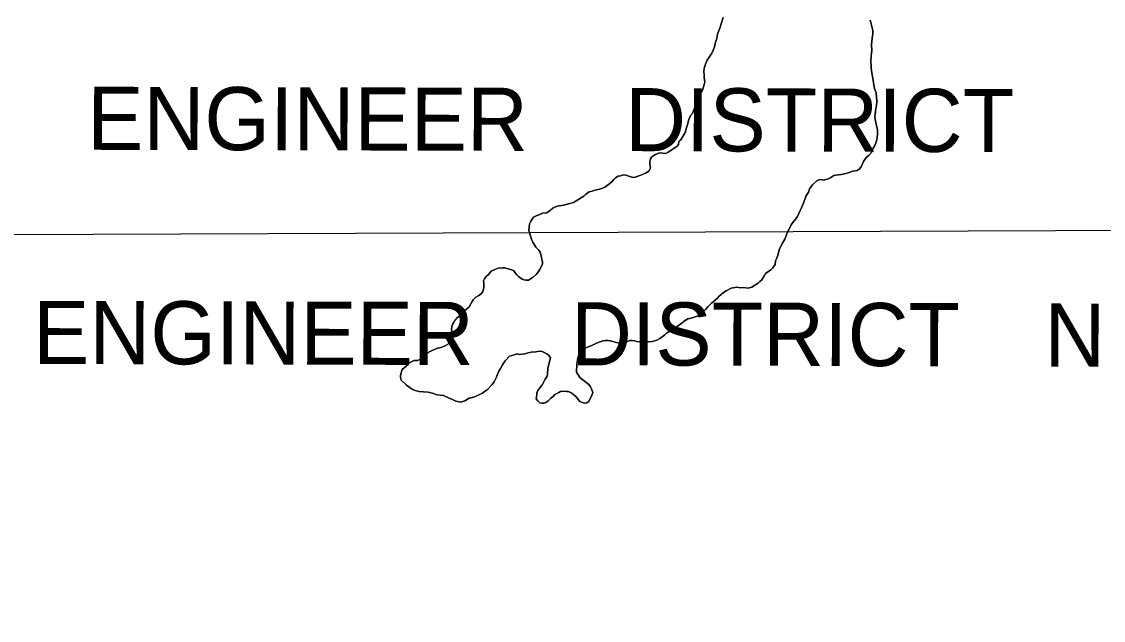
# Model space of a CAD drawing. Extents: x 3172297 to 3210190, y 958463 to 983887.
# Drawn here: x 3188356 to 3190071, y 963866 to 964815 of the extents above; entities that cross this region are included whole.
import ezdxf

# ---------------------------------------------------------------- set-up
doc = ezdxf.new("R2010")
doc.units = 0
for name, color, linetype in [('V-SITE-VEGE', 7, 'Continuous'), ('V-TOPO-BNDY', 7, 'Continuous'), ('V-TOPO-GNAM-IDEN', 7, 'Continuous'), ('V-TOPO-SHOR', 7, 'Continuous')]:
    doc.layers.add(name, color=color, linetype=linetype)

msp = doc.modelspace()

# ---------------------------------------------------------------- linework, layer by layer
at = {"layer": 'V-SITE-VEGE'}
for points in [[(3189182, 964431.1), (3189181.9, 964434.5), (3189180.9, 964438.3), (3189180.2, 964442.1), (3189178.5, 964449.7), (3189176.4, 964452.8), (3189171.5, 964457.9), (3189166.7, 964465.5), (3189164.6, 964470.3), (3189163.2, 964475.5), (3189160.4, 964484.4), (3189160.8, 964489.6), (3189161.4, 964494.8), (3189163.5, 964499.2), (3189167.9, 964505.5), (3189172.1, 964507.5), (3189177.9, 964509.6), (3189182, 964511.4), (3189188.9, 964512.4), (3189194.4, 964516.2), (3189198.2, 964519.7), (3189201.3, 964521.4), (3189205.1, 964522.5), (3189215.1, 964524.2), (3189231.2, 964528.4), (3189247.4, 964538.8), (3189250.1, 964541.2), (3189256, 964545.7), (3189260.8, 964546.7), (3189264.9, 964548.1), (3189272.2, 964549.5), (3189275.6, 964550.6), (3189279.7, 964552.3), (3189282.5, 964553.7), (3189288.7, 964558.6), (3189293.1, 964562.4), (3189295.2, 964565.1), (3189297.6, 964567.5), (3189302.1, 964570.3), (3189305.8, 964571), (3189310.3, 964572.4), (3189313.8, 964572.1), (3189323.8, 964568.7), (3189327.2, 964568.3), (3189330.3, 964569), (3189334.4, 964570.8), (3189340.3, 964572.8), (3189345.1, 964575.3), (3189350.3, 964578.4), (3189353, 964583.2), (3189352.3, 964589.1), (3189352.3, 964593.2), (3189353.3, 964597.7), (3189354.7, 964600.4), (3189360.5, 964604.9), (3189368.1, 964607.4), (3189377.4, 964606.4), (3189381.2, 964608.1), (3189394.9, 964617.5), (3189397.7, 964620.6), (3189398.3, 964625), (3189399.7, 964626.8), (3189401.1, 964627.8), (3189407.9, 964639.5), (3189410.3, 964647.1), (3189412, 964651.9), (3189412.7, 964656.4), (3189413.7, 964659.9), (3189416.8, 964666.4), (3189419.5, 964669.9), (3189423.6, 964679.9), (3189424, 964685.1), (3189425.3, 964690.2), (3189429.4, 964697.1), (3189433.2, 964703), (3189435.3, 964706.8), (3189437.6, 964713.7), (3189439.4, 964719.9), (3189438.7, 964723.7), (3189438.3, 964727.5), (3189438.3, 964730.9), (3189437.6, 964736.4), (3189438.2, 964741.6), (3189440.3, 964748.1), (3189443, 964754.4), (3189445.1, 964757.5), (3189448.5, 964761.9), (3189450.6, 964765.1), (3189452.6, 964769.9), (3189454, 964773.7), (3189455.7, 964779.5), (3189456.4, 964782.6), (3189458.1, 964788.8), (3189458.7, 964792.6), (3189460.1, 964797.1), (3189462.8, 964804.7), (3189468.3, 964821.6)], [(3189701.5, 964817.5), (3189702.2, 964814.1), (3189705.3, 964801.4), (3189705.4, 964795.8), (3189704.7, 964789.3), (3189703.3, 964779), (3189703.7, 964769), (3189703.4, 964765.2), (3189702.7, 964762.1), (3189702.7, 964758), (3189702.4, 964754.8), (3189702.8, 964741.8), (3189703.8, 964734.2), (3189706.3, 964722.5), (3189707.3, 964714.9), (3189708.4, 964709.4), (3189710.8, 964702.2), (3189711.9, 964689.1), (3189711.2, 964681.9), (3189710.2, 964677.7), (3189709.5, 964673.6), (3189708.5, 964664.3), (3189709.6, 964657.7), (3189712.7, 964643.6), (3189713.1, 964636.4), (3189712.1, 964627.8), (3189710.4, 964623.3), (3189708, 964618.1), (3189705.9, 964614.7), (3189703.2, 964607.8), (3189699.4, 964602.9), (3189695, 964599.8), (3189690.9, 964593.6), (3189686.8, 964585.3), (3189684, 964581.2), (3189680.9, 964579.1), (3189673.7, 964578.1), (3189667.8, 964576), (3189662.7, 964574.6), (3189655.1, 964572.8), (3189646.8, 964572.1), (3189643.7, 964571.1), (3189638.9, 964568.3), (3189634.5, 964566.2), (3189627.6, 964564.1), (3189622.8, 964564.8), (3189619.7, 964564.4), (3189616.9, 964562.7), (3189609.7, 964556.8), (3189605.2, 964550.3), (3189603.5, 964544.8), (3189599.4, 964538.5), (3189598.4, 964534.8), (3189596.3, 964528.9), (3189591.9, 964519.2), (3189590.5, 964515.8), (3189586.1, 964506.5), (3189583.3, 964502.7), (3189578.5, 964496.8), (3189576.1, 964493), (3189572, 964484.4), (3189570.3, 964481.3), (3189566.2, 964470.6), (3189562.8, 964465.4), (3189560.7, 964461.6), (3189559, 964457.5), (3189557.3, 964454), (3189557, 964453.7), (3189554.9, 964444.7), (3189552.9, 964439.5), (3189551.2, 964436.1), (3189550.5, 964430.2), (3189546.4, 964424.4), (3189543.7, 964421.6), (3189535.4, 964416.1), (3189533.7, 964413), (3189528.9, 964405.7), (3189526.5, 964403.3), (3189523.7, 964400.9), (3189519.6, 964397.8), (3189513.8, 964394.3), (3189507.9, 964392.9), (3189500.3, 964393.6), (3189495.5, 964393.5), (3189490.7, 964394.2), (3189481.1, 964392.5), (3189473.2, 964388.3), (3189469, 964385.9), (3189461.5, 964379.3), (3189459.4, 964376.9), (3189452.5, 964371), (3189449.8, 964368.9)], [(3189159, 964290.5), (3189153.8, 964288.8), (3189144.9, 964287.7), (3189141.8, 964288.4), (3189137, 964287.3), (3189129.7, 964285.2), (3189122.9, 964277.6), (3189121.8, 964275.9), (3189120.1, 964273.8), (3189118.4, 964271.1), (3189115.3, 964265.2), (3189112.6, 964261.1), (3189109.9, 964254.9), (3189108.8, 964251.8), (3189105.1, 964244.2), (3189102, 964240), (3189094.4, 964231.7), (3189089.6, 964228.3), (3189089.3, 964228.3), (3189086.9, 964226.2), (3189073.1, 964220), (3189065.5, 964218.2), (3189059, 964214.4), (3189052.5, 964212), (3189044.5, 964213.7), (3189038.3, 964216.7), (3189033.9, 964218.4), (3189025.2, 964222.6), (3189014.5, 964223.5), (3189009, 964225.9), (3189000.8, 964228), (3188985.9, 964229), (3188978.7, 964231), (3188975.2, 964232.7), (3188972.1, 964234.8), (3188966.6, 964239.2), (3188958, 964246.8), (3188956.9, 964250.9), (3188956.9, 964254), (3188957.9, 964258.8), (3188959.3, 964263.7), (3188968.9, 964272), (3188970.3, 964273.7), (3188975.1, 964276.5), (3188978.5, 964277.9), (3188984.1, 964278.2), (3188989.2, 964280.3), (3188993.3, 964282.7), (3188998.8, 964287.9), (3189002.3, 964291.7), (3189015.3, 964297.6), (3189019.5, 964298), (3189022.6, 964299), (3189027.7, 964301.4), (3189031.2, 964303.5), (3189036, 964308.4), (3189036.6, 964315.2), (3189038, 964320.4), (3189038.3, 964323.5), (3189037.6, 964328), (3189038.3, 964331.8), (3189039.3, 964335.2), (3189040.7, 964338), (3189042.4, 964340.7), (3189046.5, 964345.6), (3189049.3, 964348), (3189054.1, 964353.2), (3189062.3, 964359.8), (3189065.8, 964362.9), (3189070.6, 964371.5), (3189072.3, 964374.3), (3189076.4, 964378.7), (3189080.9, 964381.2), (3189085.3, 964384.3), (3189087.4, 964387.4), (3189089.1, 964393.3), (3189089.1, 964400.8), (3189088.7, 964404.3), (3189090.1, 964407.7), (3189092.5, 964411.2), (3189096.6, 964414.6), (3189100.7, 964419.5), (3189106.6, 964422.6), (3189111.7, 964424.3), (3189117.9, 964425), (3189121.7, 964425.1), (3189133.1, 964422), (3189136.5, 964420.3), (3189138.9, 964417.2), (3189141.4, 964413.7), (3189144.1, 964411.3), (3189149.7, 964407.2), (3189153.1, 964405.9), (3189156.2, 964405.2), (3189159.6, 964405.5), (3189163.1, 964407.3), (3189167.2, 964410), (3189171.7, 964414.5), (3189174.4, 964417.6), (3189177.9, 964422.1), (3189182, 964431.1)], [(3189449.8, 964368.9), (3189444, 964363.1), (3189440.5, 964358.9), (3189437.4, 964355.8), (3189435, 964353.4), (3189431.9, 964351), (3189428.5, 964348.9), (3189417.5, 964345.4), (3189412.3, 964344), (3189408.2, 964341.6), (3189401, 964336.1), (3189397.6, 964333.6), (3189390, 964327.8), (3189384.8, 964325), (3189378.6, 964321.2), (3189375.2, 964318.1), (3189367.7, 964312.9), (3189363.2, 964310.4), (3189355.6, 964308.4), (3189350.1, 964307.7), (3189344.9, 964307.3), (3189340.1, 964307.3), (3189331.2, 964308.3), (3189328.1, 964309.3), (3189323.6, 964310), (3189320.5, 964309.6), (3189319.1, 964309.3), (3189314.6, 964307.5), (3189310.8, 964306.5), (3189304.3, 964305.8), (3189299.1, 964306.5), (3189295, 964307.8), (3189289.5, 964309.2), (3189285.3, 964309.9), (3189281.9, 964309.8), (3189277.8, 964309.1), (3189267.4, 964305.7), (3189262.3, 964302.9), (3189257.5, 964300.8), (3189250.2, 964298), (3189247.5, 964296.6), (3189243.4, 964293.9), (3189242.7, 964293.2), (3189238.9, 964285.6), (3189238.2, 964282.1), (3189237.2, 964278.7), (3189236.6, 964272.1), (3189235.9, 964259.7), (3189237.3, 964256.7), (3189239.7, 964253.9), (3189241.4, 964251.2), (3189255.6, 964239.8), (3189258, 964236.4), (3189259.8, 964233.3), (3189261.5, 964227.1), (3189260.1, 964223), (3189255.3, 964213.3), (3189252.3, 964210.9), (3189248.1, 964210.2), (3189243.6, 964211.9), (3189240.9, 964213.3), (3189234.7, 964220.8), (3189231.5, 964223.6), (3189230.5, 964224.9), (3189227.4, 964227), (3189223.3, 964228.7), (3189220.2, 964229), (3189214.3, 964229.4), (3189210.5, 964229), (3189207.8, 964227.3), (3189202.6, 964224.5), (3189201.6, 964224.2), (3189199.2, 964221.7), (3189195.4, 964218.6), (3189193.3, 964216.2), (3189190.2, 964213.8), (3189187.1, 964211.7), (3189184.4, 964210.3), (3189181.3, 964210.3), (3189177.9, 964211), (3189174.4, 964214.1), (3189172, 964217.5), (3189173, 964223.7), (3189173, 964226.8), (3189174.7, 964230.3), (3189181.2, 964239.6), (3189181.9, 964239.9), (3189186, 964248.6), (3189189.1, 964253.1), (3189189.8, 964256.5), (3189190.4, 964265.5), (3189191.4, 964269.9), (3189193.1, 964276.1), (3189194.5, 964282.7), (3189191.7, 964286.5), (3189189, 964288.9), (3189181.7, 964292.3), (3189177.2, 964293), (3189171.4, 964291.9), (3189163.8, 964291.2), (3189159, 964290.5)]]:
    msp.add_lwpolyline(points, dxfattribs=at)
at = {"layer": 'V-TOPO-BNDY'}
msp.add_lwpolyline([(3186048.8, 963896), (3186249.6, 964470), (3198733.3, 964517.6), (3198114.7, 963866.1)], dxfattribs=at)
at = {"layer": 'V-TOPO-SHOR'}
for points in [[(3189468.3, 964821.6), (3189462.8, 964804.7), (3189460.1, 964797.1), (3189458.7, 964792.6), (3189458.1, 964788.8), (3189456.4, 964782.6), (3189455.7, 964779.5), (3189454, 964773.7), (3189452.6, 964769.9), (3189450.6, 964765.1), (3189448.5, 964761.9), (3189445.1, 964757.5), (3189443, 964754.4), (3189440.3, 964748.1), (3189438.2, 964741.6), (3189437.6, 964736.4), (3189438.3, 964730.9), (3189438.3, 964727.5), (3189438.7, 964723.7), (3189439.4, 964719.9), (3189437.6, 964713.7), (3189435.3, 964706.8), (3189433.2, 964703), (3189429.4, 964697.1), (3189425.3, 964690.2), (3189424, 964685.1), (3189423.6, 964679.9), (3189419.5, 964669.9), (3189416.8, 964666.4), (3189413.7, 964659.9), (3189412.7, 964656.4), (3189412, 964651.9), (3189410.3, 964647.1), (3189407.9, 964639.5), (3189401.1, 964627.8), (3189399.7, 964626.8), (3189398.3, 964625), (3189397.7, 964620.6), (3189394.9, 964617.5), (3189381.2, 964608.1), (3189377.4, 964606.4), (3189368.1, 964607.4), (3189360.5, 964604.9), (3189354.7, 964600.4), (3189353.3, 964597.7), (3189352.3, 964593.2), (3189352.3, 964589.1), (3189353, 964583.2), (3189350.3, 964578.4), (3189345.1, 964575.3), (3189340.3, 964572.8), (3189334.4, 964570.8), (3189330.3, 964569), (3189327.2, 964568.3), (3189323.8, 964568.7), (3189313.8, 964572.1), (3189310.3, 964572.4), (3189305.8, 964571), (3189302.1, 964570.3), (3189297.6, 964567.5), (3189295.2, 964565.1), (3189293.1, 964562.4)], [(3189452.5, 964371), (3189459.4, 964376.9), (3189461.5, 964379.3), (3189469, 964385.9), (3189473.2, 964388.3), (3189481.1, 964392.5), (3189490.7, 964394.2), (3189495.5, 964393.5), (3189500.3, 964393.6), (3189507.9, 964392.9), (3189513.8, 964394.3), (3189519.6, 964397.8), (3189523.7, 964400.9), (3189526.5, 964403.3), (3189528.9, 964405.7), (3189533.7, 964413), (3189535.4, 964416.1), (3189543.7, 964421.6), (3189546.4, 964424.4), (3189550.5, 964430.2), (3189551.2, 964436.1), (3189552.9, 964439.5), (3189554.9, 964444.7), (3189557, 964453.7), (3189557.3, 964454), (3189559, 964457.5), (3189560.7, 964461.6), (3189562.8, 964465.4), (3189566.2, 964470.6), (3189570.3, 964481.3), (3189572, 964484.4), (3189576.1, 964493), (3189578.5, 964496.8), (3189583.3, 964502.7), (3189586.1, 964506.5), (3189590.5, 964515.8), (3189591.9, 964519.2), (3189596.3, 964528.9), (3189598.4, 964534.8), (3189599.4, 964538.6), (3189603.5, 964544.8), (3189605.2, 964550.3), (3189609.7, 964556.8), (3189616.9, 964562.7), (3189619.7, 964564.4), (3189622.8, 964564.8), (3189627.6, 964564.1), (3189634.5, 964566.2), (3189638.9, 964568.3), (3189643.7, 964571.1), (3189646.8, 964572.1), (3189655.1, 964572.8), (3189662.7, 964574.6), (3189667.8, 964576), (3189673.7, 964578.1), (3189680.9, 964579.1), (3189684, 964581.2), (3189686.8, 964585.3), (3189690.9, 964593.6), (3189695, 964599.8), (3189699.4, 964602.9), (3189703.2, 964607.8), (3189705.9, 964614.7), (3189708, 964618.1), (3189710.4, 964623.3), (3189712.1, 964627.8), (3189713.1, 964636.4), (3189712.7, 964643.6), (3189709.6, 964657.7), (3189708.5, 964664.3), (3189709.5, 964673.6), (3189710.2, 964677.7), (3189711.2, 964681.9), (3189711.9, 964689.1), (3189710.8, 964702.2), (3189708.4, 964709.4), (3189707.3, 964714.9), (3189706.3, 964722.5), (3189703.8, 964734.2), (3189702.8, 964741.8), (3189702.4, 964754.8), (3189702.7, 964758), (3189702.7, 964762.1), (3189703.4, 964765.2), (3189703.7, 964769), (3189703.3, 964779), (3189704.7, 964789.3), (3189705.4, 964795.8), (3189705.3, 964801.4), (3189702.2, 964814.1), (3189701.5, 964817.5)], [(3189293.1, 964562.4), (3189288.7, 964558.6), (3189282.5, 964553.7), (3189279.7, 964552.3), (3189275.6, 964550.6), (3189272.2, 964549.5), (3189264.9, 964548.1), (3189260.8, 964546.7), (3189256, 964545.7), (3189250.1, 964541.2), (3189247.4, 964538.8), (3189231.2, 964528.4), (3189215.1, 964524.2), (3189205.1, 964522.5), (3189201.3, 964521.4), (3189198.2, 964519.7), (3189194.4, 964516.2), (3189188.9, 964512.4), (3189182, 964511.4), (3189177.9, 964509.6), (3189172.1, 964507.5), (3189167.9, 964505.5), (3189163.5, 964499.2), (3189161.4, 964494.8), (3189160.8, 964489.6), (3189160.4, 964484.4), (3189163.2, 964475.5), (3189164.6, 964470.3), (3189166.7, 964465.5), (3189171.5, 964457.9), (3189176.4, 964452.8), (3189178.5, 964449.7), (3189180.2, 964442.1), (3189180.9, 964438.3), (3189181.9, 964434.5), (3189182, 964431.1), (3189177.9, 964422.1), (3189174.4, 964417.6), (3189171.7, 964414.5), (3189167.2, 964410), (3189163.1, 964407.3), (3189159.7, 964405.5), (3189156.2, 964405.2), (3189153.1, 964405.9), (3189149.7, 964407.2), (3189144.1, 964411.3), (3189141.4, 964413.7), (3189138.9, 964417.2), (3189136.5, 964420.3), (3189133.1, 964422), (3189121.7, 964425.1), (3189117.9, 964425), (3189111.7, 964424.3), (3189106.6, 964422.6), (3189100.7, 964419.5), (3189096.6, 964414.6), (3189092.5, 964411.2), (3189090.1, 964407.7), (3189088.7, 964404.3), (3189089.1, 964400.8), (3189089.1, 964393.3), (3189087.4, 964387.4), (3189085.3, 964384.3), (3189080.9, 964381.2), (3189076.4, 964378.7), (3189072.3, 964374.3), (3189070.6, 964371.5), (3189065.8, 964362.9), (3189062.3, 964359.8), (3189054.1, 964353.2), (3189049.3, 964348), (3189046.5, 964345.6), (3189042.4, 964340.8), (3189040.7, 964338), (3189039.3, 964335.2), (3189038.3, 964331.8), (3189037.6, 964328), (3189038.3, 964323.5), (3189038, 964320.4), (3189036.6, 964315.2), (3189036, 964308.4), (3189031.2, 964303.5), (3189027.7, 964301.4), (3189022.6, 964299), (3189019.5, 964298), (3189015.3, 964297.6), (3189002.3, 964291.7), (3188998.8, 964287.9), (3188993.3, 964282.7), (3188989.2, 964280.3), (3188984.1, 964278.2), (3188978.5, 964277.9), (3188975.1, 964276.5), (3188970.3, 964273.7), (3188968.9, 964272), (3188959.3, 964263.7), (3188957.9, 964258.8), (3188956.9, 964254), (3188956.9, 964250.9), (3188958, 964246.8), (3188966.6, 964239.2)], [(3189277.8, 964309.1), (3189281.9, 964309.8), (3189285.3, 964309.9), (3189289.5, 964309.2), (3189295, 964307.8), (3189299.1, 964306.5), (3189304.3, 964305.8), (3189310.8, 964306.5), (3189314.6, 964307.5), (3189319.1, 964309.3), (3189320.5, 964309.6), (3189323.6, 964310), (3189328.1, 964309.3), (3189331.2, 964308.3), (3189340.1, 964307.3), (3189344.9, 964307.3), (3189350.1, 964307.7), (3189355.6, 964308.4), (3189363.2, 964310.4), (3189367.7, 964312.9), (3189375.2, 964318.1), (3189378.6, 964321.2), (3189384.8, 964325), (3189390, 964327.8), (3189397.6, 964333.6), (3189401, 964336.1), (3189408.2, 964341.6), (3189412.3, 964344), (3189417.5, 964345.4), (3189428.5, 964348.9), (3189431.9, 964351), (3189435, 964353.4), (3189437.4, 964355.8), (3189440.5, 964358.9), (3189444, 964363.1), (3189449.8, 964368.9), (3189452.5, 964371)], [(3188966.6, 964239.2), (3188972.1, 964234.8), (3188975.2, 964232.7), (3188978.7, 964231), (3188985.9, 964229), (3189000.8, 964228), (3189009, 964225.9), (3189014.5, 964223.5), (3189025.2, 964222.6), (3189033.9, 964218.4), (3189038.3, 964216.7), (3189044.5, 964213.7), (3189052.5, 964212), (3189059, 964214.4), (3189065.5, 964218.2), (3189073.1, 964220), (3189086.9, 964226.2), (3189089.3, 964228.3), (3189089.6, 964228.3), (3189094.4, 964231.7), (3189102, 964240), (3189105.1, 964244.2), (3189108.8, 964251.8), (3189109.9, 964254.9), (3189112.6, 964261.1), (3189115.3, 964265.2), (3189118.4, 964271.1), (3189120.1, 964273.8), (3189121.8, 964275.9), (3189122.9, 964277.6), (3189129.7, 964285.2), (3189137, 964287.3), (3189141.8, 964288.4), (3189144.9, 964287.7), (3189153.8, 964288.8), (3189159, 964290.5), (3189163.8, 964291.2), (3189171.4, 964291.9), (3189177.2, 964293), (3189181.7, 964292.3), (3189189, 964288.9), (3189191.7, 964286.5), (3189194.5, 964282.7), (3189193.1, 964276.1), (3189191.4, 964269.9), (3189190.4, 964265.5), (3189189.8, 964256.5), (3189189.1, 964253.1), (3189186, 964248.6), (3189181.9, 964239.9), (3189181.2, 964239.6), (3189174.7, 964230.3), (3189173, 964226.8), (3189173, 964223.7), (3189172, 964217.5), (3189174.4, 964214.1), (3189177.9, 964211), (3189181.3, 964210.3), (3189184.4, 964210.3), (3189187.1, 964211.7), (3189190.2, 964213.8), (3189193.3, 964216.2), (3189195.4, 964218.6), (3189199.2, 964221.7), (3189201.6, 964224.2), (3189202.6, 964224.5), (3189207.8, 964227.3), (3189210.5, 964229), (3189214.3, 964229.4), (3189220.2, 964229), (3189223.3, 964228.7), (3189227.4, 964227), (3189230.5, 964224.9), (3189231.5, 964223.6), (3189234.7, 964220.8), (3189240.9, 964213.3), (3189243.6, 964211.9), (3189248.1, 964210.2), (3189252.3, 964210.9), (3189255.3, 964213.3), (3189260.1, 964223), (3189261.5, 964227.1), (3189259.8, 964233.3), (3189258, 964236.4), (3189255.6, 964239.8), (3189241.4, 964251.2), (3189239.7, 964253.9), (3189237.3, 964256.7), (3189235.9, 964259.7), (3189236.6, 964272.1), (3189237.2, 964278.7), (3189238.2, 964282.1), (3189238.9, 964285.6), (3189242.7, 964293.2), (3189243.4, 964293.9), (3189247.5, 964296.6), (3189250.2, 964298), (3189257.5, 964300.8), (3189262.3, 964302.9), (3189267.4, 964305.7), (3189277.8, 964309.1)]]:
    msp.add_lwpolyline(points, dxfattribs=at)

# ---------------------------------------------------------------- texts
at = {"layer": 'V-TOPO-GNAM-IDEN'}
for s, p in [('ENGINEER', (3188460.2, 964612.1)), ('DISTRICT', (3189312.8, 964610)), ('ENGINEER', (3188374.5, 964272.6)), ('DISTRICT', (3189227, 964270.5)), ('NEW ', (3189977.4, 964268.6))]:
    msp.add_text(s, height=100, rotation=359.8583, dxfattribs=at).set_placement(p)

doc.saveas('drawing.dxf')
